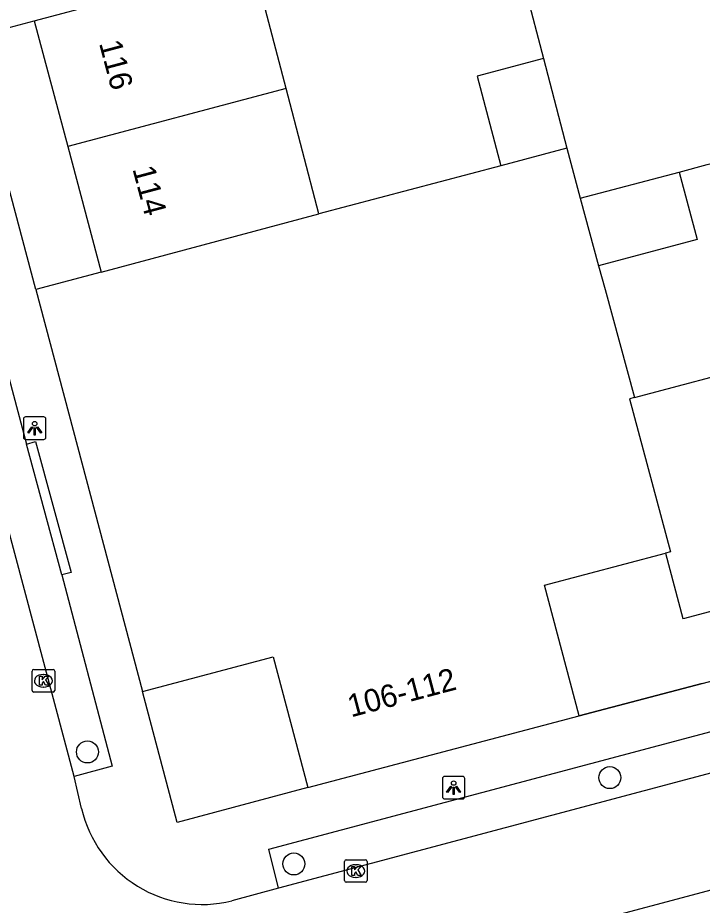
# Model space of a CAD drawing. Extents: x 162542 to 163144, y 380786 to 381511.
# Drawn here: x 162655.35 to 162685.75, y 381106.58 to 381145.96 of the extents above; entities that cross this region are included whole.
import ezdxf

# ---------------------------------------------------------------- set-up
doc = ezdxf.new("R2010")
doc.units = 0
for name, color, linetype in [('IMGEO_Boom', 7, 'Continuous'), ('IMGEO_Kolk', 7, 'Continuous'), ('IMGEO_Lichtpunt', 7, 'Continuous'), ('IMGEO_Muur', 7, 'Continuous'), ('IMGEO_Pand', 7, 'Continuous'), ('IMGEO_Pand_nummerreeks', 7, 'Continuous'), ('IMGEO_Rijbaan_lokaal_open', 7, 'Continuous'), ('IMGEO_Voetpad_open', 7, 'Continuous')]:
    doc.layers.add(name, color=color, linetype=linetype)

msp = doc.modelspace()

# ---------------------------------------------------------------- linework, layer by layer
at = {"layer": 'IMGEO_Boom'}
for centre in [(162658.444, 381113.388), (162681.641, 381112.249), (162667.608, 381108.419)]:
    msp.add_circle(centre, 0.489, dxfattribs=at)
at = {"layer": 'IMGEO_Kolk'}
for p, q in [((162655.986, 381116.118), (162655.986, 381116.97)), ((162656.061, 381117.044), (162656.913, 381117.044)), ((162656.474, 381116.824), (162656.499, 381116.824)), ((162656.987, 381116.97), (162656.987, 381116.118)), ((162656.913, 381116.044), (162656.061, 381116.044)), ((162656.497, 381116.264), (162656.472, 381116.264)), ((162669.858, 381107.675), (162669.858, 381108.527)), ((162669.933, 381108.601), (162670.785, 381108.601)), ((162670.859, 381108.527), (162670.859, 381107.675)), ((162670.346, 381108.381), (162670.371, 381108.381)), ((162670.369, 381107.821), (162670.344, 381107.821)), ((162670.785, 381107.601), (162669.933, 381107.601))]:
    msp.add_line(p, q, dxfattribs=at)
for points in [[(162655.986, 381116.118), (162655.986, 381116.97)], [(162656.061, 381117.044), (162656.913, 381117.044)], [(162656.987, 381116.97), (162656.987, 381116.118)], [(162656.307, 381116.744), (162656.43, 381116.744), (162656.43, 381116.593), (162656.56, 381116.744), (162656.724, 381116.744), (162656.578, 381116.593), (162656.731, 381116.344), (162656.579, 381116.344), (162656.494, 381116.508), (162656.43, 381116.441), (162656.43, 381116.344), (162656.307, 381116.344), (162656.307, 381116.744)], [(162656.913, 381116.044), (162656.061, 381116.044)], [(162669.858, 381107.675), (162669.858, 381108.527)], [(162669.933, 381108.601), (162670.785, 381108.601)], [(162670.859, 381108.527), (162670.859, 381107.675)], [(162670.179, 381108.301), (162670.302, 381108.301), (162670.302, 381108.15), (162670.432, 381108.301), (162670.596, 381108.301), (162670.45, 381108.15), (162670.603, 381107.901), (162670.451, 381107.901), (162670.366, 381108.065), (162670.302, 381107.998), (162670.302, 381107.901), (162670.179, 381107.901), (162670.179, 381108.301)], [(162670.785, 381107.601), (162669.933, 381107.601)]]:
    msp.add_lwpolyline(points, dxfattribs=at)
for centre, start, end in [((162656.063, 381116.968), 91.552, 178.448), ((162656.063, 381116.968), 91.552, 178.448), ((162656.911, 381116.968), 1.552, 88.448), ((162656.911, 381116.968), 1.552, 88.448), ((162656.063, 381116.12), 181.552, 268.448), ((162656.063, 381116.12), 181.552, 268.448), ((162656.911, 381116.12), 271.552, 358.448), ((162656.911, 381116.12), 271.552, 358.448), ((162669.935, 381108.525), 91.552, 178.448), ((162669.935, 381108.525), 91.552, 178.448), ((162670.783, 381108.525), 1.552, 88.448), ((162670.783, 381108.525), 1.552, 88.448), ((162669.935, 381107.677), 181.552, 268.448), ((162669.935, 381107.677), 181.552, 268.448), ((162670.783, 381107.677), 271.552, 358.448), ((162670.783, 381107.677), 271.552, 358.448)]:
    msp.add_arc(centre, 0.0765, start, end, dxfattribs=at)
for centre, major_axis, ratio, start_param, end_param in [((162656.473, 381116.544), (-0.387, 0.002), 0.722429, 4.712389, 7.853982), ((162656.498, 381116.544), (-0.39, 0.002), 0.717154, 1.570796, 4.712389), ((162670.345, 381108.101), (-0.387, 0.002), 0.722429, 4.712389, 7.853982), ((162670.37, 381108.101), (-0.39, 0.002), 0.717154, 1.570796, 4.712389)]:
    msp.add_ellipse(centre, major_axis=major_axis, ratio=ratio, start_param=start_param, end_param=end_param, dxfattribs=at)
at = {"layer": 'IMGEO_Lichtpunt'}
for p, q in [((162656.503, 381128.25), (162655.695, 381128.25)), ((162656.503, 381128.25), (162655.695, 381128.25)), ((162655.601, 381128.155), (162655.601, 381127.348)), ((162655.601, 381128.155), (162655.601, 381127.348)), ((162656.597, 381127.348), (162656.597, 381128.155)), ((162656.597, 381127.348), (162656.597, 381128.155)), ((162655.695, 381127.254), (162656.503, 381127.254)), ((162655.695, 381127.254), (162656.503, 381127.254)), ((162674.205, 381112.206), (162674.205, 381111.399)), ((162674.205, 381112.206), (162674.205, 381111.399)), ((162675.107, 381112.301), (162674.299, 381112.301)), ((162675.107, 381112.301), (162674.299, 381112.301)), ((162675.201, 381111.399), (162675.201, 381112.206)), ((162675.201, 381111.399), (162675.201, 381112.206)), ((162674.299, 381111.305), (162675.107, 381111.305)), ((162674.299, 381111.305), (162675.107, 381111.305))]:
    msp.add_line(p, q, dxfattribs=at)
for points in [[(162655.975, 381127.819), (162656.014, 381127.791), (162655.826, 381127.529), (162655.788, 381127.556), (162655.975, 381127.819)], [(162656.187, 381127.791), (162656.225, 381127.818), (162656.412, 381127.556), (162656.373, 381127.528), (162656.187, 381127.791)], [(162656.077, 381127.771), (162656.124, 381127.771), (162656.124, 381127.449), (162656.077, 381127.449), (162656.077, 381127.771)], [(162674.579, 381111.87), (162674.618, 381111.842), (162674.43, 381111.58), (162674.392, 381111.607), (162674.579, 381111.87)], [(162674.681, 381111.822), (162674.728, 381111.822), (162674.728, 381111.5), (162674.681, 381111.5), (162674.681, 381111.822)], [(162674.791, 381111.842), (162674.829, 381111.869), (162675.016, 381111.607), (162674.977, 381111.579), (162674.791, 381111.842)]]:
    msp.add_lwpolyline(points, dxfattribs=at)
for centre in [(162656.1, 381127.953), (162674.704, 381112.004)]:
    msp.add_circle(centre, 0.0994, dxfattribs=at)
for centre, start, end in [((162655.695, 381128.155), 90, 180), ((162655.695, 381128.155), 90, 180), ((162656.503, 381128.155), 0, 90), ((162656.503, 381128.155), 0, 90), ((162655.695, 381127.348), 180, 270), ((162655.695, 381127.348), 180, 270), ((162656.503, 381127.348), 270, 0), ((162656.503, 381127.348), 270, 360), ((162674.299, 381112.206), 90, 180), ((162674.299, 381112.206), 90, 180), ((162675.107, 381112.206), 0, 90), ((162675.107, 381112.206), 0, 90), ((162674.299, 381111.399), 180, 270), ((162674.299, 381111.399), 180, 270), ((162675.107, 381111.399), 270, 0), ((162675.107, 381111.399), 270, 360)]:
    msp.add_arc(centre, 0.0946, start, end, dxfattribs=at)
at = {"layer": 'IMGEO_Muur'}
for points in [[(162685.734, 381116.428), (162680.279, 381114.986)], [(162668.23, 381111.802), (162662.432, 381110.26), (162660.887, 381116.07)]]:
    msp.add_lwpolyline(points, dxfattribs=at)
at = {"layer": 'IMGEO_Pand'}
for points in [[(162656.081, 381145.826), (162665.799, 381148.416)], [(162667.262, 381142.828), (162665.799, 381148.416)], [(162653.181, 381145.057), (162656.081, 381145.826)], [(162656.081, 381145.826), (162657.565, 381140.248)], [(162678.692, 381144.15), (162675.742, 381143.365), (162676.798, 381139.397)], [(162678.692, 381144.15), (162679.725, 381140.171)], [(162667.262, 381142.828), (162657.565, 381140.248)], [(162668.718, 381137.261), (162667.262, 381142.828)], [(162657.565, 381140.248), (162659.049, 381134.67)], [(162679.725, 381140.171), (162676.798, 381139.397)], [(162679.725, 381140.171), (162680.329, 381137.953)], [(162676.798, 381139.397), (162668.718, 381137.261)], [(162680.329, 381137.953), (162684.722, 381139.117)], [(162684.722, 381139.117), (162685.516, 381136.121), (162681.144, 381134.962)], [(162680.329, 381137.953), (162681.144, 381134.962)], [(162659.049, 381134.67), (162668.718, 381137.261)], [(162681.144, 381134.962), (162681.431, 381133.908), (162682.737, 381129.114)], [(162659.049, 381134.67), (162656.145, 381133.899)], [(162656.145, 381133.899), (162657.803, 381127.667), (162660.887, 381116.07)], [(162682.737, 381129.114), (162688.324, 381130.598)], [(162682.737, 381129.114), (162682.52, 381129.057), (162684.328, 381122.262), (162684.115, 381122.206)], [(162680.279, 381114.986), (162678.746, 381120.787), (162684.115, 381122.206)], [(162684.115, 381122.206), (162684.888, 381119.301), (162684.977, 381119.324), (162690.904, 381120.902)], [(162660.887, 381116.07), (162666.685, 381117.612), (162668.23, 381111.802)], [(162668.23, 381111.802), (162680.279, 381114.986)]]:
    msp.add_lwpolyline(points, dxfattribs=at)
at = {"layer": 'IMGEO_Rijbaan_lokaal_open'}
for points in [[(162677.911, 381147.157), (162678.692, 381144.15)], [(162657.855, 381112.29), (162649.38, 381144.042)], [(162684.722, 381139.117), (162685.969, 381139.448), (162687.17, 381139.767)], [(162774.201, 381135.871), (162666.934, 381107.34)], [(162658.181, 381110.883), (162657.855, 381112.29)], [(162674.634, 381104.211), (162692.09, 381108.85)], [(162666.934, 381107.34), (162664.853, 381106.777)]]:
    msp.add_lwpolyline(points, dxfattribs=at)
msp.add_arc((162663.543, 381112.122), 5.503, 193.012, 283.7711, dxfattribs=at)
at = {"layer": 'IMGEO_Voetpad_open'}
for points in [[(162656.145, 381133.899), (162653.181, 381145.057)], [(162651.083, 381144.497), (162655.734, 381127.049)], [(162680.279, 381114.986), (162685.734, 381116.428), (162749.869, 381133.472)], [(162666.934, 381107.34), (162666.499, 381109.073), (162750.234, 381131.33)], [(162655.734, 381127.049), (162656.14, 381127.159), (162657.722, 381121.348), (162657.309, 381121.241)], [(162657.309, 381121.241), (162655.734, 381127.049)], [(162657.309, 381121.241), (162659.54, 381112.76), (162657.855, 381112.29)], [(162668.23, 381111.802), (162662.432, 381110.26), (162660.887, 381116.07)]]:
    msp.add_lwpolyline(points, dxfattribs=at)

# ---------------------------------------------------------------- texts
at = {"layer": 'IMGEO_Pand_nummerreeks'}
for s, rotation, p in [('116', 284.8987, (162658.951, 381144.837)), ('114', 284.8987, (162660.435, 381139.259)), ('106-112', 14.8017, (162670.148, 381114.916))]:
    msp.add_text(s, height=1, rotation=rotation, dxfattribs=at).set_placement(p)

doc.saveas('drawing.dxf')
